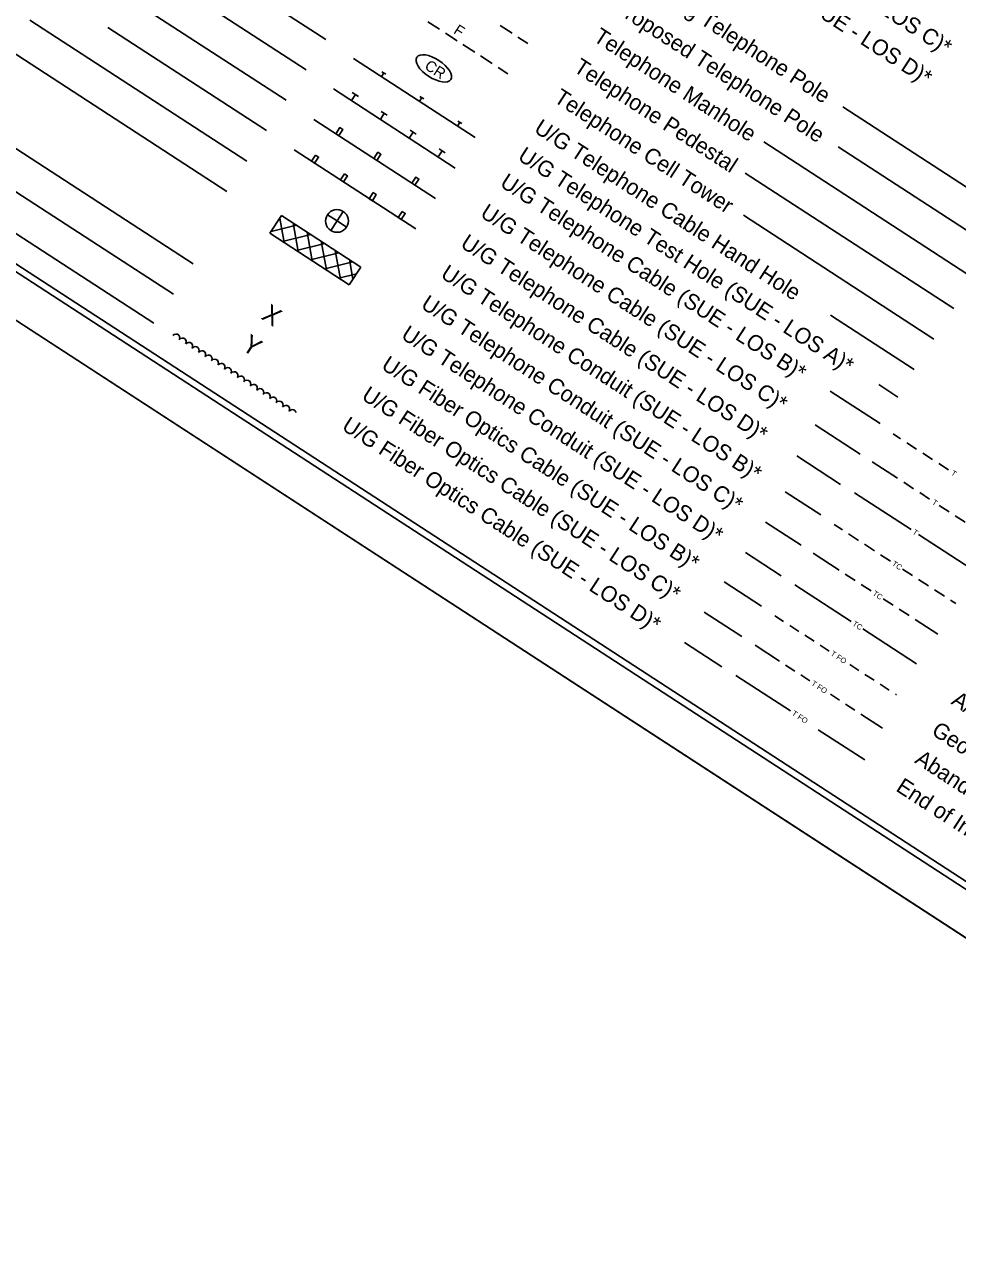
# Model space of a CAD drawing. Extents: x 2291197 to 2302790, y 592892 to 604246.
# Drawn here: x 2293741 to 2295799, y 592892 to 595574 of the extents above; entities that cross this region are included whole.
import ezdxf

# ---------------------------------------------------------------- set-up
doc = ezdxf.new("R2010")
doc.units = 0
for name, color, linetype in [('Default', 7, 'Continuous'), ('Prop Shade Light', 7, 'Continuous'), ('Sheet Cutting Line CELL', 7, 'Continuous'), ('Sheet Plot Border Inside CELL', 7, 'Continuous'), ('Sheet Plot Border Outside CELL', 7, 'Continuous'), ('Sheet Symbology CELL', 7, 'Continuous')]:
    doc.layers.add(name, color=color, linetype=linetype)

# ---------------------------------------------------------------- blocks, each defined once
blk = doc.blocks.new('EQCIR')
at = {"layer": 'Sheet Symbology CELL'}
for p, q in [((-0.25, 0), (0, 0)), ((0, 0.25), (0, 0)), ((0, 0), (0, -0.25)), ((0, 0), (0.25, 0))]:
    blk.add_line(p, q, dxfattribs=at)
for start, end in [(89.9944, 179.9989), (359.9944, 89.9989), (179.9944, 269.9989), (269.9944, 359.9989)]:
    blk.add_arc((0, 0), 0.25, start, end, dxfattribs=at)
blk = doc.blocks.new('CR')
at = {"layer": 'Prop WCC CELL'}
blk.add_ellipse((0.02, -0.02), major_axis=(5.61, 0), ratio=0.462467, dxfattribs=at)
blk.add_text('CR', height=3, dxfattribs=at).set_placement((-2.34, -1.5))
blk = doc.blocks.new('PLAN SHEET SYMBOLOGY - New')
at = {"layer": 'Sheet Cutting Line CELL'}
blk.add_line((1437692.56, 920633.15), (1439376.56, 920633.15), dxfattribs=at)
at = {"layer": 'Sheet Plot Border Inside CELL'}
blk.add_lwpolyline([(1437705.56, 920655.6), (1439372.06, 920655.6), (1439372.06, 921710.7), (1437705.56, 921710.7)], close=True, dxfattribs=at)
at = {"layer": 'Sheet Plot Border Outside CELL'}
blk.add_lwpolyline([(1437692.56, 920633.15), (1439376.56, 920633.15), (1439376.56, 921733.15), (1437692.56, 921733.15)], close=True, dxfattribs=at)
at = {"layer": 'Sheet Symbology CELL'}
for p, q in [((1438875.46, 920980.31), (1438763.57, 920980.31)), ((1438875.46, 920960.31), (1438773.39, 920960.31)), ((1438875.46, 920940.31), (1438737.59, 920940.31)), ((1438875.46, 920920.31), (1438738.29, 920920.31)), ((1438588.53, 920914.92), (1438580.68, 920914.92)), ((1438598.83, 920914.92), (1438592.43, 920914.92)), ((1438875.46, 920900.31), (1438750.23, 920900.31)), ((1438553.78, 920894.92), (1438546.18, 920894.92)), ((1438565.53, 920894.92), (1438557.73, 920894.92)), ((1438576.98, 920894.92), (1438569.23, 920894.92)), ((1438588.53, 920894.92), (1438580.68, 920894.92)), ((1438598.83, 920894.92), (1438592.43, 920894.92)), ((1438875.46, 920880.31), (1438820.42, 920880.31)), ((1438876.27, 920862.63), (1438863.62, 920862.63)), ((1438504.3, 920856.09), (1438389.46, 920856.09)), ((1438522.83, 920855.51), (1438602.83, 920855.51)), ((1438539.96, 920858.01), (1438542.46, 920858.01)), ((1438541.21, 920855.51), (1438541.21, 920858.01)), ((1438564.96, 920858.01), (1438567.46, 920858.01)), ((1438566.21, 920855.51), (1438566.21, 920858.01)), ((1438589.96, 920858.01), (1438592.46, 920858.01)), ((1438591.21, 920855.51), (1438591.21, 920858.01)), ((1438876, 920845.01), (1438843.22, 920845.01)), ((1438885.01, 920844.21), (1438890.04, 920844.21)), ((1438894.04, 920844.21), (1438900.54, 920844.21)), ((1438904.54, 920844.21), (1438911.04, 920844.21)), ((1438915.04, 920844.21), (1438921.54, 920844.21)), ((1438504.3, 920836.09), (1438368.06, 920836.09)), ((1438602.83, 920835.51), (1438522.83, 920835.51)), ((1438532.55, 920839.46), (1438536.55, 920839.46)), ((1438534.55, 920835.51), (1438534.55, 920839.46)), ((1438551.55, 920839.46), (1438555.55, 920839.46)), ((1438553.55, 920835.51), (1438553.55, 920839.46)), ((1438570.55, 920839.46), (1438574.55, 920839.46)), ((1438572.55, 920835.51), (1438572.55, 920839.46)), ((1438589.55, 920839.46), (1438593.55, 920839.46)), ((1438591.55, 920835.51), (1438591.55, 920839.46)), ((1438876, 920825.01), (1438846.38, 920825.01)), ((1438883.76, 920825.01), (1438900.54, 920825.01)), ((1438904.54, 920825.01), (1438911.04, 920825.01)), ((1438915.04, 920825.01), (1438921.54, 920825.01)), ((1438927.94, 920825.01), (1438934.44, 920825.01)), ((1438938.44, 920825.01), (1438944.94, 920825.01)), ((1438504.3, 920816.09), (1438400, 920816.09)), ((1438522.83, 920815.51), (1438602.83, 920815.51)), ((1438876, 920805.01), (1438847.15, 920805.01)), ((1438885.01, 920805.36), (1438922.14, 920805.36)), ((1438927.14, 920805.36), (1438969.52, 920805.36)), ((1438504.3, 920796.09), (1438400, 920796.09)), ((1438522.83, 920795.51), (1438602.83, 920795.51)), ((1438876, 920785.01), (1438852.54, 920785.01)), ((1438885.01, 920784.58), (1438890.6, 920784.58)), ((1438894.6, 920784.58), (1438901.1, 920784.58)), ((1438905.1, 920784.58), (1438911.6, 920784.58)), ((1438915.6, 920784.58), (1438922.1, 920784.58)), ((1438930.1, 920784.58), (1438936.6, 920784.58)), ((1438940.6, 920784.58), (1438947.1, 920784.58)), ((1438951.1, 920784.58), (1438957.6, 920784.58)), ((1438961.6, 920784.58), (1438965.01, 920784.58)), ((1438504.3, 920776.09), (1438361.67, 920776.09)), ((1438536.78, 920761.37), (1438588.88, 920761.37)), ((1438536.78, 920749.67), (1438536.78, 920761.37)), ((1438536.78, 920760.77), (1438537.33, 920761.37)), ((1438536.78, 920750.82), (1438546.63, 920761.37)), ((1438546.03, 920749.67), (1438536.78, 920759.57)), ((1438555.33, 920749.67), (1438544.33, 920761.37)), ((1438544.93, 920749.67), (1438555.93, 920761.37)), ((1438564.58, 920749.67), (1438553.63, 920761.37)), ((1438554.18, 920749.67), (1438565.23, 920761.37)), ((1438573.88, 920749.67), (1438562.88, 920761.37)), ((1438563.48, 920749.67), (1438574.48, 920761.37)), ((1438583.18, 920749.67), (1438572.13, 920761.37)), ((1438572.78, 920749.67), (1438583.73, 920761.37)), ((1438588.88, 920753.42), (1438581.43, 920761.37)), ((1438588.88, 920761.37), (1438588.88, 920749.67)), ((1438876, 920765.01), (1438852.54, 920765.01)), ((1438884.06, 920765.01), (1438901.1, 920765.01)), ((1438905.1, 920765.01), (1438911.6, 920765.01)), ((1438915.6, 920765.01), (1438922.1, 920765.01)), ((1438930.1, 920765.01), (1438936.6, 920765.01)), ((1438940.6, 920765.01), (1438947.1, 920765.01)), ((1438951.1, 920765.01), (1438965.97, 920765.01)), ((1438504.3, 920756.09), (1438361.67, 920756.09)), ((1438582.03, 920749.67), (1438588.88, 920756.97)), ((1438588.88, 920749.67), (1438536.78, 920749.67)), ((1438876, 920745.01), (1438852.54, 920745.01)), ((1438885.01, 920744.96), (1438922.1, 920744.96)), ((1438929.6, 920744.96), (1438965.01, 920744.96)), ((1438876, 920725.01), (1438851.38, 920725.01)), ((1438885.01, 920724.58), (1438890.85, 920724.58)), ((1438894.85, 920724.58), (1438900.85, 920724.58)), ((1438904.85, 920724.58), (1438910.85, 920724.58)), ((1438914.85, 920724.58), (1438920.85, 920724.58)), ((1438934.35, 920724.58), (1438940.35, 920724.58)), ((1438944.35, 920724.58), (1438950.35, 920724.58)), ((1438954.35, 920724.58), (1438960.35, 920724.58)), ((1438964.35, 920724.58), (1438965.01, 920724.58)), ((1438510.43, 920712.44), (1438329.31, 920712.44)), ((1438876, 920705.01), (1438851.38, 920705.01)), ((1438884.83, 920705.01), (1438900.85, 920705.01)), ((1438904.85, 920705.01), (1438910.85, 920705.01)), ((1438914.85, 920705.01), (1438920.85, 920705.01)), ((1438934.35, 920705.01), (1438940.35, 920705.01)), ((1438944.35, 920705.01), (1438950.35, 920705.01)), ((1438954.35, 920705.01), (1438968.66, 920705.01)), ((1438510.43, 920692.44), (1438329.31, 920692.44)), ((1438885.01, 920685.34), (1438920.89, 920685.34)), ((1438876, 920685.01), (1438851.38, 920685.01)), ((1438939.39, 920684.96), (1438970.01, 920684.96)), ((1438510.17, 920673.18), (1438297.48, 920673.18)), ((1438522.56, 920673.18), (1438522.86, 920674.13)), ((1438522.86, 920674.13), (1438523.46, 920674.78)), ((1438523.46, 920674.78), (1438524.26, 920675.23)), ((1438524.26, 920675.23), (1438525.21, 920675.23)), ((1438525.21, 920675.23), (1438526.01, 920674.73)), ((1438526.01, 920674.73), (1438526.56, 920674.08)), ((1438526.56, 920674.08), (1438526.76, 920673.23)), ((1438526.81, 920673.18), (1438527.11, 920674.13)), ((1438527.11, 920674.13), (1438527.71, 920674.78)), ((1438527.71, 920674.78), (1438528.51, 920675.23)), ((1438528.51, 920675.23), (1438529.46, 920675.23)), ((1438529.46, 920675.23), (1438530.26, 920674.73)), ((1438530.26, 920674.73), (1438530.81, 920674.08)), ((1438530.81, 920674.08), (1438531.01, 920673.23)), ((1438531.06, 920673.18), (1438531.36, 920674.13)), ((1438531.36, 920674.13), (1438531.96, 920674.78)), ((1438531.96, 920674.78), (1438532.76, 920675.23)), ((1438532.76, 920675.23), (1438533.71, 920675.23)), ((1438533.71, 920675.23), (1438534.51, 920674.73)), ((1438534.51, 920674.73), (1438535.06, 920674.08)), ((1438535.06, 920674.08), (1438535.26, 920673.23)), ((1438535.31, 920673.18), (1438535.61, 920674.13)), ((1438535.61, 920674.13), (1438536.21, 920674.78)), ((1438536.21, 920674.78), (1438537.01, 920675.23)), ((1438537.01, 920675.23), (1438537.96, 920675.23)), ((1438537.96, 920675.23), (1438538.76, 920674.73)), ((1438538.76, 920674.73), (1438539.31, 920674.08)), ((1438539.31, 920674.08), (1438539.51, 920673.23)), ((1438539.56, 920673.18), (1438539.86, 920674.13)), ((1438539.86, 920674.13), (1438540.46, 920674.78)), ((1438540.46, 920674.78), (1438541.26, 920675.23)), ((1438541.26, 920675.23), (1438542.21, 920675.23)), ((1438542.21, 920675.23), (1438543.01, 920674.73)), ((1438543.01, 920674.73), (1438543.56, 920674.08)), ((1438543.56, 920674.08), (1438543.76, 920673.23)), ((1438543.81, 920673.18), (1438544.11, 920674.13)), ((1438544.11, 920674.13), (1438544.71, 920674.78)), ((1438544.71, 920674.78), (1438545.51, 920675.23)), ((1438545.51, 920675.23), (1438546.46, 920675.23)), ((1438546.46, 920675.23), (1438547.26, 920674.73)), ((1438547.26, 920674.73), (1438547.81, 920674.08)), ((1438547.81, 920674.08), (1438548.01, 920673.23)), ((1438548.06, 920673.18), (1438548.36, 920674.13)), ((1438548.36, 920674.13), (1438548.96, 920674.78)), ((1438548.96, 920674.78), (1438549.76, 920675.23)), ((1438549.76, 920675.23), (1438550.71, 920675.23)), ((1438550.71, 920675.23), (1438551.51, 920674.73)), ((1438551.51, 920674.73), (1438552.06, 920674.08)), ((1438552.06, 920674.08), (1438552.26, 920673.23)), ((1438552.31, 920673.18), (1438552.61, 920674.13)), ((1438552.61, 920674.13), (1438553.21, 920674.78)), ((1438553.21, 920674.78), (1438554.01, 920675.23)), ((1438554.01, 920675.23), (1438554.96, 920675.23)), ((1438554.96, 920675.23), (1438555.76, 920674.73)), ((1438555.76, 920674.73), (1438556.31, 920674.08)), ((1438556.31, 920674.08), (1438556.51, 920673.23)), ((1438556.56, 920673.18), (1438556.86, 920674.13)), ((1438556.86, 920674.13), (1438557.46, 920674.78)), ((1438557.46, 920674.78), (1438558.26, 920675.23)), ((1438558.26, 920675.23), (1438559.21, 920675.23)), ((1438559.21, 920675.23), (1438560.01, 920674.73)), ((1438560.01, 920674.73), (1438560.56, 920674.08)), ((1438560.56, 920674.08), (1438560.76, 920673.23)), ((1438560.81, 920673.18), (1438561.11, 920674.13)), ((1438561.11, 920674.13), (1438561.71, 920674.78)), ((1438561.71, 920674.78), (1438562.51, 920675.23)), ((1438562.51, 920675.23), (1438563.46, 920675.23)), ((1438563.46, 920675.23), (1438564.26, 920674.73)), ((1438564.26, 920674.73), (1438564.81, 920674.08)), ((1438564.81, 920674.08), (1438565.01, 920673.23)), ((1438565.06, 920673.18), (1438565.36, 920674.13)), ((1438565.36, 920674.13), (1438565.96, 920674.78)), ((1438565.96, 920674.78), (1438566.76, 920675.23)), ((1438566.76, 920675.23), (1438567.71, 920675.23)), ((1438567.71, 920675.23), (1438568.51, 920674.73)), ((1438568.51, 920674.73), (1438569.06, 920674.08)), ((1438569.06, 920674.08), (1438569.26, 920673.23)), ((1438569.31, 920673.18), (1438569.61, 920674.13)), ((1438569.61, 920674.13), (1438570.21, 920674.78)), ((1438570.21, 920674.78), (1438571.01, 920675.23)), ((1438571.01, 920675.23), (1438571.96, 920675.23)), ((1438571.96, 920675.23), (1438572.76, 920674.73)), ((1438572.76, 920674.73), (1438573.31, 920674.08)), ((1438573.31, 920674.08), (1438573.51, 920673.23)), ((1438573.56, 920673.18), (1438573.86, 920674.13)), ((1438573.86, 920674.13), (1438574.46, 920674.78)), ((1438574.46, 920674.78), (1438575.26, 920675.23)), ((1438575.26, 920675.23), (1438576.21, 920675.23)), ((1438576.21, 920675.23), (1438577.01, 920674.73)), ((1438577.01, 920674.73), (1438577.56, 920674.08)), ((1438577.56, 920674.08), (1438577.76, 920673.23)), ((1438577.81, 920673.18), (1438578.11, 920674.13)), ((1438578.11, 920674.13), (1438578.71, 920674.78)), ((1438578.71, 920674.78), (1438579.51, 920675.23)), ((1438579.51, 920675.23), (1438580.46, 920675.23)), ((1438580.46, 920675.23), (1438581.26, 920674.73)), ((1438581.26, 920674.73), (1438581.81, 920674.08)), ((1438581.81, 920674.08), (1438582.01, 920673.23)), ((1438582.06, 920673.18), (1438582.36, 920674.13)), ((1438582.36, 920674.13), (1438582.96, 920674.78)), ((1438582.96, 920674.78), (1438583.76, 920675.23)), ((1438583.76, 920675.23), (1438584.71, 920675.23)), ((1438584.71, 920675.23), (1438585.51, 920674.73)), ((1438585.51, 920674.73), (1438586.06, 920674.08)), ((1438586.06, 920674.08), (1438586.26, 920673.23)), ((1438586.31, 920673.18), (1438586.61, 920674.13)), ((1438586.61, 920674.13), (1438587.21, 920674.78)), ((1438587.21, 920674.78), (1438588.01, 920675.23)), ((1438588.01, 920675.23), (1438588.96, 920675.23)), ((1438588.96, 920675.23), (1438589.76, 920674.73)), ((1438589.76, 920674.73), (1438590.31, 920674.08)), ((1438590.31, 920674.08), (1438590.51, 920673.23)), ((1438590.56, 920673.18), (1438590.86, 920674.13)), ((1438590.86, 920674.13), (1438591.46, 920674.78)), ((1438591.46, 920674.78), (1438592.26, 920675.23)), ((1438592.26, 920675.23), (1438593.21, 920675.23)), ((1438593.21, 920675.23), (1438594.01, 920674.73)), ((1438594.01, 920674.73), (1438594.56, 920674.08)), ((1438594.56, 920674.08), (1438594.76, 920673.23)), ((1438594.81, 920673.18), (1438595.11, 920674.13)), ((1438595.11, 920674.13), (1438595.71, 920674.78)), ((1438595.71, 920674.78), (1438596.51, 920675.23)), ((1438596.51, 920675.23), (1438597.46, 920675.23)), ((1438597.46, 920675.23), (1438598.26, 920674.73)), ((1438598.26, 920674.73), (1438598.81, 920674.08)), ((1438598.81, 920674.08), (1438599.01, 920673.23)), ((1438599.06, 920673.18), (1438599.36, 920674.13)), ((1438599.36, 920674.13), (1438599.96, 920674.78)), ((1438599.96, 920674.78), (1438600.76, 920675.23)), ((1438600.76, 920675.23), (1438601.71, 920675.23)), ((1438601.71, 920675.23), (1438602.51, 920674.73)), ((1438602.51, 920674.73), (1438602.56, 920674.68))]:
    blk.add_line(p, q, dxfattribs=at)
for points in [[(1439359.56, 921708.15), (1437859.56, 921708.15), (1437859.56, 920659.17), (1439359.56, 920659.17)], [(1438537.3, 920815.51), (1438539.3, 920815.51), (1438539.3, 920819.51), (1438537.3, 920819.51)], [(1438562.3, 920815.51), (1438564.3, 920815.51), (1438564.3, 920819.51), (1438562.3, 920819.51)], [(1438587.3, 920815.51), (1438589.3, 920815.51), (1438589.3, 920819.51), (1438587.3, 920819.51)], [(1438534.29, 920799.51), (1438536.29, 920799.51), (1438536.29, 920795.51), (1438534.29, 920795.51)], [(1438553.29, 920799.51), (1438555.29, 920799.51), (1438555.29, 920795.51), (1438553.29, 920795.51)], [(1438572.29, 920799.51), (1438574.29, 920799.51), (1438574.29, 920795.51), (1438572.29, 920795.51)], [(1438591.29, 920799.51), (1438593.29, 920799.51), (1438593.29, 920795.51), (1438591.29, 920795.51)]]:
    blk.add_lwpolyline(points, close=True, dxfattribs=at)
at = {"layer": 'Default'}
for name, p, xscale, yscale in [('CR', (1438562.9, 920875.15), 2, 2), ('EQCIR', (1438564.05, 920775.5), 25, 25)]:
    blk.add_blockref(name, p, dxfattribs=dict(at, xscale=xscale, yscale=yscale))
at = {"layer": 'Sheet Symbology CELL'}
for s, height, p in [('U/G Power Line Test Hole (SUE - LOS A)*', 8.75, (1438628.02, 921072.83)), ('U/G Power Line (SUE - LOS C)*', 8.75, (1438627.77, 921034.65)), ('U/G Power Line (SUE - LOS D)*', 8.75, (1438627.79, 921014.63)), ('Existing Telephone Pole', 8.75, (1438627.74, 920975.77)), ('Proposed Telephone Pole', 8.75, (1438627.74, 920955.77)), ('Telephone Manhole', 8.75, (1438627.74, 920935.77)), ('Telephone Pedestal', 8.75, (1438627.74, 920915.77)), ('F', 5.93, (1438560.98, 920897.28)), ('Telephone Cell Tower', 8.75, (1438627.76, 920895.77)), ('U/G Telephone Cable Hand Hole', 8.75, (1438627.76, 920875.77)), ('U/G Telephone Test Hole (SUE - LOS A)*', 8.75, (1438628.57, 920858.09)), ('U/G Telephone Cable (SUE - LOS B)*', 8.75, (1438628.3, 920840.47)), ('T', 3, (1438923.79, 920842.71)), ('U/G Telephone Cable (SUE - LOS C)*', 8.75, (1438628.3, 920820.47)), ('T', 3, (1438923.79, 920823.51)), ('U/G Telephone Cable (SUE - LOS D)*', 8.75, (1438628.3, 920800.47)), ('T', 3, (1438923.69, 920803.86)), ('U/G Telephone Conduit (SUE - LOS B)*', 8.75, (1438628.3, 920780.47)), ('TC', 3, (1438923.7, 920783.08)), ('U/G Telephone Conduit (SUE - LOS C)*', 8.75, (1438628.3, 920760.47)), ('TC', 3, (1438923.7, 920763.51)), ('U/G Telephone Conduit (SUE - LOS D)*', 8.75, (1438628.3, 920740.47)), ('TC', 3, (1438923.45, 920743.46)), ('A/G Tank; Water, Gas, Oil', 8.75, (1438992.49, 920736.79)), ('U/G Fiber Optics Cable (SUE - LOS B)*', 8.75, (1438628.3, 920720.47)), ('T FO', 3, (1438922.35, 920723.08)), ('Geoenvironmental Boring', 8.75, (1438992.49, 920716.79)), ('X', 10, (1438557.83, 920707.44)), ('U/G Fiber Optics Cable (SUE - LOS C)*', 8.75, (1438628.3, 920700.47)), ('T FO', 3, (1438922.35, 920703.51)), ('Abandoned According to Utility Records', 8.75, (1438993.31, 920698.65)), ('Y', 10, (1438557.83, 920687.44)), ('U/G Fiber Optics Cable (SUE - LOS D)*', 8.75, (1438628.3, 920680.47)), ('T FO', 3, (1438922.39, 920683.84))]:
    blk.add_text(s, height=height, dxfattribs=at).set_placement(p)
blk.add_text('End of Information', height=8.75, rotation=360, dxfattribs=at).set_placement((1438993.03, 920680.01))

msp = doc.modelspace()

# ---------------------------------------------------------------- linework, layer by layer
at = {"layer": 'Sheet Cutting Line CELL'}
msp.add_line((2291197.2, 596563.1), (2296844.8, 592891.8), dxfattribs=at)

# ---------------------------------------------------------------- block references
at = {"layer": 'Prop Shade Light', "xscale": 4, "yscale": 3.9999999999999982, "rotation": -33.02629958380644}
msp.add_blockref('PLAN SHEET SYMBOLOGY - New', (-4537434.8, 643359.8), dxfattribs=at)

doc.saveas('drawing.dxf')
